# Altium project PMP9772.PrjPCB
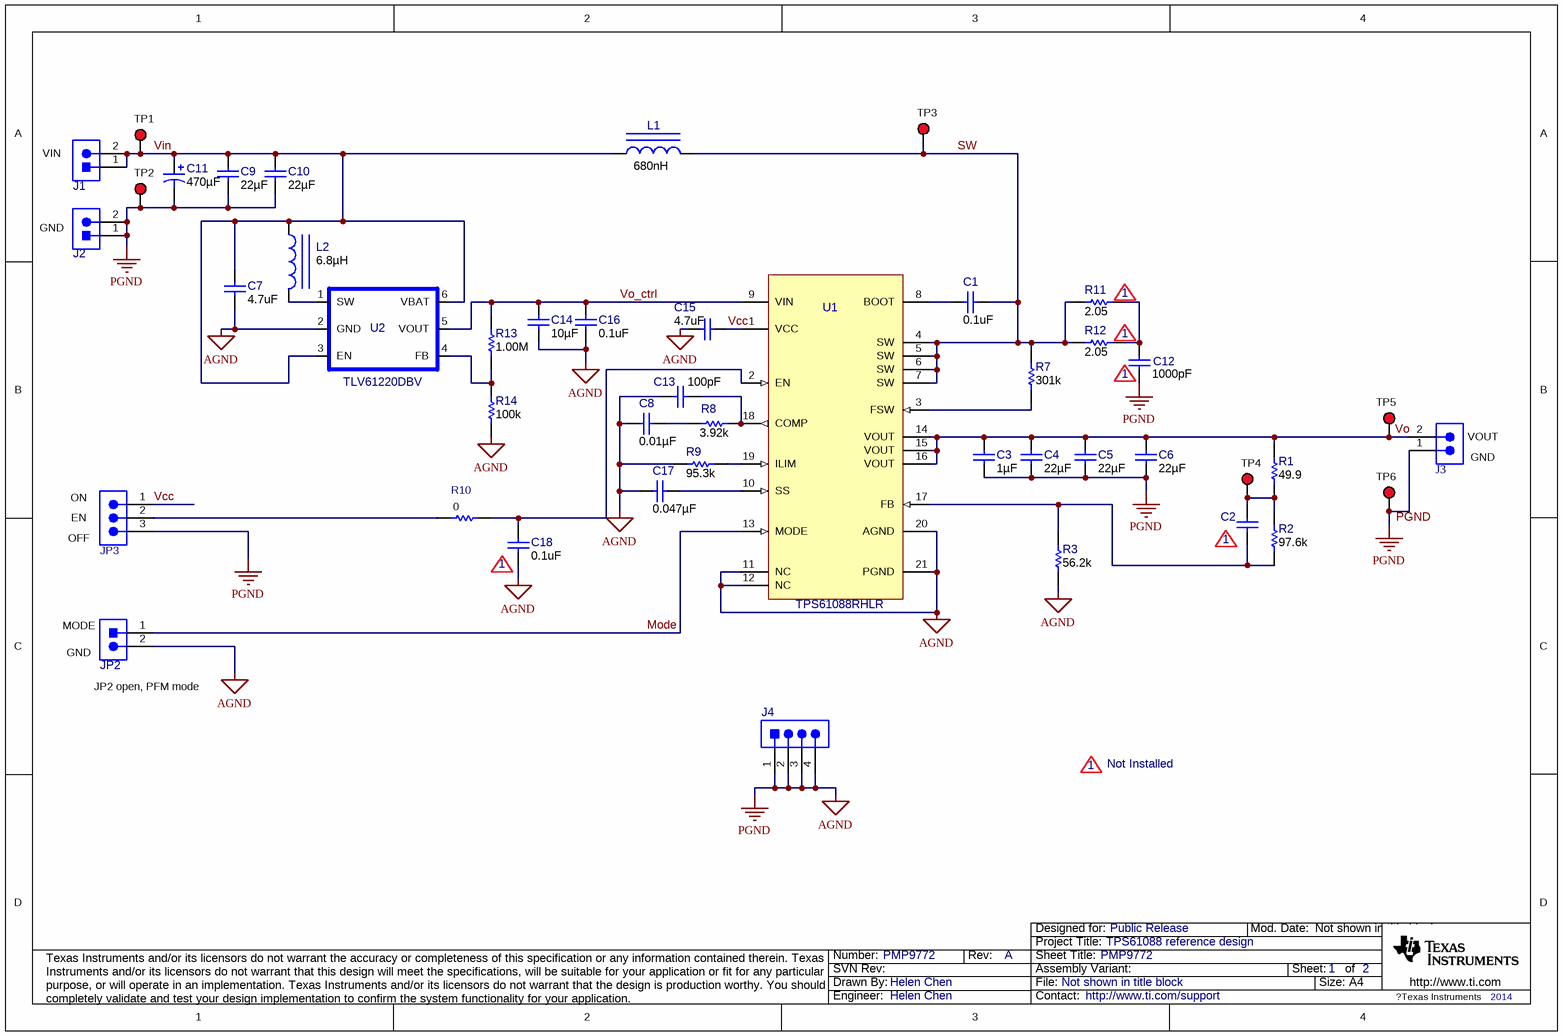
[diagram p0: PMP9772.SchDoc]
CopyrightYear: 2014; PCB_Layout: Helen Chen; PCB_Rev: A; PRJ_Customer: Public Release; PRJ_Engineer: Helen Chen; PRJ_Number: PMP9772; PRJ_Title: TPS61088 reference design; SCH_Rev: A; TechSupport: http://www.ti.com/support
2 sheets, 63 parts. Net scope: global (net labels, ports and power ports of the same name join across sheets).
Board file: PMP9772.PcbDoc
Sheets:
  PMP9772.SchDoc
  PMP9772_Hardware.SchDoc

## Sheet PMP9772.SchDoc: PMP9772
size A4; Date: Not shown in title block; ApprovedBy: Not shown in title block; CheckedBy: Not shown in title block; Author: Not shown in title block; CompanyName: TI; DrawnBy: Helen Chen; Engineer: Not shown in title block; Organization: Not shown in title block; Address1: Not shown in title block; Address2: Not shown in title block; Address3: Not shown in title block; Address4: Not shown in title block; DocumentNumber: 1; Revision: A; SheetNumber: 1; SheetTotal: 2; PageSetup: Record=PageOptions¦CenterHorizontal=True¦CenterVertical=True¦PrintScale=0.68¦XCorrection=1.00¦YCorrection=1.00¦PrintKind=0¦BorderSize=5000000¦LeftOffset=0¦BottomOffset=0¦Orientation=2¦PaperLength=1000¦PaperWidth=1000¦Scale=100¦PaperSource=15¦PrintQuality=600¦MediaType=1¦DitherType=10¦PaperKind=Letter¦PrintScaleMode=1

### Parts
C1  ValueDisplayed: 0.1uF  [0402]  (hidden comment: GRM155R61C104KA88D)
C2  GRM1555C1H470FA01D  [0402]  (value not drawn)
C3  ValueDisplayed: 1µF  [0603]  (hidden comment: GRM188R71E105KA12D)
C4  ValueDisplayed: 22µF  [1206]  (hidden comment: GRM31CR61C226KE15L)
C5  ValueDisplayed: 22µF  [1206]  (hidden comment: GRM31CR61C226KE15L)
C6  ValueDisplayed: 22µF  [1206]  (hidden comment: GRM31CR61C226KE15L)
C7  ValueDisplayed: 4.7uF  [0603]  (hidden comment: 0603ZD475KAT2A)
C8  ValueDisplayed: 0.01µF  [0402]  (hidden comment: GRM155R71C103KA01D)
C9  ValueDisplayed: 22µF  [0805_HV]  (hidden comment: C2012X5R0J226M)
C10  ValueDisplayed: 22µF  [0805_HV]  (hidden comment: C2012X5R0J226M)
C11  ValueDisplayed: 470µF  [7343-20]  (hidden comment: 6TPE470MAZU)
C12  ValueDisplayed: 1000pF  [0603]  (hidden comment: GRM188R72A102KA01D)
C13  ValueDisplayed: 100pF  [0402]  (hidden comment: GRM1555C1H101JA01D)
C14  ValueDisplayed: 10µF  [0603]  (hidden comment: C1608X5R1A106M)
C15  ValueDisplayed: 4.7uF  [0603]  (hidden comment: 0603ZD475KAT2A)
C16  ValueDisplayed: 0.1uF  [0402]  (hidden comment: GRM155R61C104KA88D)
C17  ValueDisplayed: 0.047µF  [0402]  (hidden comment: GRM155R71C473KA01D)
C18  ValueDisplayed: 0.1uF  [0402]  (hidden comment: GRM155R61C104KA88D)
J1  ED555/2DS  [TERM_BLK_ED555-2DS]  (value not drawn)
J2  ED555/2DS  [TERM_BLK_ED555-2DS]  (value not drawn)
J3  ED555/2DS  [TERM_BLK_ED555-2DS]  (value not drawn)
J4  TSW-104-07-G-S  [TSW-104-07-G-S]  (value not drawn)
JP2  PEC02SAAN  [CONN_PEC02SAAN]  (value not drawn)
JP3  PEC03SAAN  [CONN_PEC03SAAN]  (value not drawn)
L1  ValueDisplayed: 680nH  [CDMC8D28]  (hidden comment: CDMC8D28NP-R68MC)
L2  ValueDisplayed: 6.8µH  [LQH3NP_G0]  (hidden comment: LQH3NPN6R8NG0)
R1  value 49.9  [0402]  (hidden comment: CRCW040249R9FKED)
R2  ValueDisplayed: 97.6k  [0402]  (hidden comment: CRCW040297K6FKED)
R3  ValueDisplayed: 56.2k  [0402]  (hidden comment: CRCW040256K2FKED)
R7  ValueDisplayed: 301k  [0402]  (hidden comment: CRCW0402301KFKED)
R8  ValueDisplayed: 3.92k  [0402]  (hidden comment: CRCW04023K92FKED)
R9  ValueDisplayed: 95.3k  [0402]  (hidden comment: CRCW040295K3FKED)
R10  value 0  [0402]  (hidden comment: RC0402JR-070RL)
R11  ValueDisplayed: 2.05  [0603]  (hidden comment: CRCW06032R05FKEA)
R12  ValueDisplayed: 2.05  [0603]  (hidden comment: CRCW06032R05FKEA)
R13  ValueDisplayed: 1.00M  [0402]  (hidden comment: CRCW04021M00FKED)
R14  value 100k  [0402]  (hidden comment: CRCW0402100KFKED)
TP1  5010  [Keystone5010]  (value not drawn)
TP2  5010  [Keystone5010]  (value not drawn)
TP3  5010  [Keystone5010]  (value not drawn)
TP4  5010  [Keystone5010]  (value not drawn)
TP5  5010  [Keystone5010]  (value not drawn)
TP6  5010  [Keystone5010]  (value not drawn)
U1  TPS61088RHLR  [RHL0020A]
U2  TLV61220DBV  [DBV-6]

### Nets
AGND: C3.2 C4.2 C5.2 C6.2 C7.1 C8.2 C9.2 C10.2 C11.2(-) C12.2 C13.2 C14.2 C15.1 C16.2 C17.1 C18.2 J2.1 J2.2 J3.1 J4.1 J4.2 J4.3 J4.4 JP2.2 JP3.3 R3.1 R9.1 R14.1 TP2.1 TP6.1 U1.11(NC) U1.12(NC) U1.20(AGND) U1.21(PGND) U2.2(GND)  [also labelled PGND]
Mode: JP2.1 U1.13(MODE)
SW: C1.1 L1.2 R7.2 R11.1 R12.1 TP3.1 U1.4(SW) U1.5(SW) U1.6(SW) U1.7(SW)
Vcc: C15.2 JP3.1 U1.1(VCC)
Vin: C7.2 C9.1 C10.1 C11.1(+) J1.1 J1.2 L1.1 L2.1 TP1.1 U2.3(EN) U2.6(VBAT)
Vo: C3.1 C4.1 C5.1 C6.1 J3.2 R1.2 TP5.1 U1.14(VOUT) U1.15(VOUT) U1.16(VOUT)
Vo_ctrl: C14.1 C16.1 R13.2 U1.9(VIN) U2.5(VOUT)
NetC1_2: C1.2 U1.8(BOOT)
NetC2_1: C2.1 R1.1 R2.2 TP4.1
NetC2_2: C2.2 R2.1 R3.2 U1.17(FB)
NetC8_1: C8.1 R8.1
NetC12_1: C12.1 R11.2 R12.2
NetC13_1: C13.1 R8.2 U1.18(COMP)
NetC17_2: C17.2 U1.10(SS)
NetC18_1: C18.1 R10.1 U1.2(EN)
NetJP3_2: JP3.2 R10.2
NetL2_2: L2.2 U2.1(SW)
NetR7_1: R7.1 U1.3(FSW)
NetR9_2: R9.2 U1.19(ILIM)
NetR13_1: R13.1 R14.2 U2.4(FB)

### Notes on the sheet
- (near J1) VIN
- (near J2) GND
- (near R11) 1
- (near R12) 1
- (near C12) 1
- (near J3) VOUT
- (near JP3) EN
- (near JP3) ON
- (near J3) GND
- (near JP3) OFF
- (near C18) 1
- (near C2) 1
- (near JP2) MODE
- (near JP2) GND
- (near JP2) JP2 open, PFM mode
- 1
- Not Installed
- Labels drawn without touching a wire or pin: PGND

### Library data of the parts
C1 C16 C18 = GRM155R61C104KA88D: CAP, CERM, 0.1uF, 16V, +/-10%, X5R, 0402; Manufacturer: MuRata; Polarized: N; CompType: Capacitor; U/M: EA; Cap_F: 0.0000001; Tolerance_%: 10; Value1: Unknown; VDC_V: 16; TaMin_C: -55; TaMax_C: 85
C2 = GRM1555C1H470FA01D: CAP, CERM, 47 pF, 50 V, +/- 1%, C0G, 0402; Manufacturer: MuRata; Polarized: N; CompType: Capacitor; Value: 47pF; U/M: EA; Cap_F: 0.000000000047; Tolerance_%: 1; Value1: Unknown; VDC_V: 50; Value2: 50V; TaMin_C: -55; TaMax_C: 125
C3 = GRM188R71E105KA12D: CAP, CERM, 1 µF, 25 V, +/- 10%, X7R, 0603; Manufacturer: MuRata; Polarized: N; CompType: Capacitor; Value: 1uF; U/M: EA; Cap_F: 0.000001; Tolerance_%: 10; Value1: Unknown; VDC_V: 25; Value2: 25V; TaMin_C: -55; TaMax_C: 125
C4-C6 = GRM31CR61C226KE15L: CAP, CERM, 22 µF, 16 V, +/- 10%, X5R, 1206; Manufacturer: MuRata; Polarized: N; CompType: Capacitor; Value: 22uF; U/M: EA; Cap_F: 0.000022; Tolerance_%: 10; Value1: Unknown; VDC_V: 16; Value2: 16V; TaMin_C: -55; TaMax_C: 85
C7 C15 = 0603ZD475KAT2A: CAP, CERM, 4.7uF, 10V, +/-10%, X5R, 0603; Manufacturer: AVX; Polarized: N; CompType: Capacitor; U/M: EA; Cap_F: 0.0000047; Tolerance_%: 10; Value1: Unknown; TaMin_C: -55; TaMax_C: 85
C8 = GRM155R71C103KA01D: CAP, CERM, 0.01 µF, 16 V, +/- 10%, X7R, 0402; Manufacturer: MuRata; Polarized: N; CompType: Capacitor; Value: 0.01uF; U/M: EA; Cap_F: 0.00000001; Tolerance_%: 10; Value1: Unknown; VDC_V: 16; Value2: 16V; TaMin_C: -55; TaMax_C: 125
C9 C10 = C2012X5R0J226M: CAP, CERM, 22 µF, 6.3 V, +/- 20%, X5R, 0805; Manufacturer: TDK; Polarized: N; CompType: Capacitor; Value: 22uF; U/M: EA; Cap_F: 0.000022; Tolerance_%: 20; ESR_ohm: 0.0018; Value1: 0.0018 ohm; VDC_V: 6.3; Value2: 6.3V; TaMin_C: -55; TaMax_C: 85; Cap_Case: 0805
C11 = 6TPE470MAZU: CAP, TA, 470 µF, 6.3 V, +/- 10%, 0.035 ohm, SMD; Manufacturer: Panasonic; Polarized: Y; CompType: Capacitor; Value: 470uF; U/M: EA; Cap_F: 0.00047; Tolerance_%: 10; VDC_V: 6.3; Value2: 6.3V; ESR_ohm: 0.035; IRMS_A: 1.7; TaMin_C: -55; TaMax_C: 105; Cap_Case: D
C12 = GRM188R72A102KA01D: CAP, CERM, 1000 pF, 100 V, +/- 10%, X7R, 0603; Manufacturer: MuRata; Polarized: N; CompType: Capacitor; Value: 1000pF; U/M: EA; Cap_F: 0.000000001; Tolerance_%: 10; Value1: Unknown; VDC_V: 100; Value2: 100V; TaMin_C: -55; TaMax_C: 125
C13 = GRM1555C1H101JA01D: CAP, CERM, 100 pF, 50 V, +/- 5%, C0G/NP0, 0402; Manufacturer: MuRata; Polarized: N; CompType: Capacitor; Value: 100pF; U/M: EA; Cap_F: 0.0000000001; Tolerance_%: 5; Value1: Unknown; VDC_V: 50; Value2: 50V; TaMin_C: -55; TaMax_C: 125
C14 = C1608X5R1A106M: CAP, CERM, 10 µF, 10 V, +/- 20%, X5R, 0603; Manufacturer: TDK; Polarized: N; CompType: Capacitor; Value: 10uF; U/M: EA; Cap_F: 0.00001; Tolerance_%: 20; ESR_ohm: 0.0078; Value1: 0.0078 ohm; VDC_V: 10; Value2: 10V; IRMS_A: 1.85; TaMin_C: -55; TaMax_C: 85
C17 = GRM155R71C473KA01D: CAP, CERM, 0.047 µF, 16 V, +/- 10%, X7R, 0402; Manufacturer: MuRata; Polarized: N; CompType: Capacitor; Value: 0.047uF; U/M: EA; Cap_F: 0.000000047; Tolerance_%: 10; Value1: Unknown; VDC_V: 16; Value2: 16V; TaMin_C: -55; TaMax_C: 125
J1-J3 = ED555/2DS: Terminal Block, 6A, 3.5mm Pitch, 2-Pos, TH; Manufacturer: On-Shore Technology; SymbolCreator: a0412235; CompType: Connector; U/M: EA
J4 = TSW-104-07-G-S: Header, 100mil, 4x1, Gold, TH; Manufacturer: Samtec; SymbolCreator: a0412235; U/M: EA
JP2 = PEC02SAAN: Header, 100mil, 2x1, Tin, TH; Manufacturer: Sullins Connector Solutions; SymbolCreator: a0412235; U/M: EA
JP3 = PEC03SAAN: Header, 100mil, 3x1, Tin plated, TH; Manufacturer: Sullins Connector Solutions; SymbolCreator: a0799628; U/M: EA
L1 = CDMC8D28NP-R68MC: Inductor, Shielded Drum Core, Metal Composite, 680 nH, 15.4 A, 0.00384 ohm, SMD; Manufacturer: Sumida; Value: 680nH; Ind_H: 680.0E-9; Imax_A: 15.4; Irms: 15.4A @ 40C rise; Isat: 16A @ 20% inductance drop; Value2: 15.4A
L2 = LQH3NPN6R8NG0: Inductor, Wirewound, Ferrite, 6.8 µH, 0.65 A, 0.45 ohm, SMD; Manufacturer: MuRata; Value: 6.8uH; Ind_H: 6.8E-6; Imax_A: 0.65; Irms: 0.71A @ 40C rise; Isat: 0.65A @ 30% inductance drop; DCR_ohm: 0.45; Value2: 0.65A
R1 = CRCW040249R9FKED: RES, 49.9 ohm, 1%, 0.063W, 0402; Manufacturer: Vishay-Dale; CompType: Resistor; Value_Code: 49R9; Tolerance_%: 1; Power_W: 0.063; VDC_V: 50; TempCo: 100 ppm/C; EIA_Code: E96; U/M: EA
R2 = CRCW040297K6FKED: RES, 97.6 k, 1%, 0.063 W, 0402; Manufacturer: Vishay-Dale; CompType: Resistor; Value: 97.6k; Res_ohm: 97600; Value_Code: 97k6; Tolerance_%: 1; Power_W: 0.063; Value2: 0.063W; VDC_V: 50; TempCo: 100 ppm/C; EIA_Code: E96; U/M: EA
R3 = CRCW040256K2FKED: RES, 56.2 k, 1%, 0.063 W, 0402; Manufacturer: Vishay-Dale; CompType: Resistor; Value: 56.2k; Res_ohm: 56200; Value_Code: 56k2; Tolerance_%: 1; Power_W: 0.063; Value2: 0.063W; VDC_V: 50; TempCo: 100 ppm/C; EIA_Code: E96; U/M: EA
R7 = CRCW0402301KFKED: RES, 301 k, 1%, 0.063 W, 0402; Manufacturer: Vishay-Dale; CompType: Resistor; Value: 301k; Res_ohm: 301000; Tolerance_%: 1; Power_W: 0.063; Value2: 0.063W; VDC_V: 50; TempCo: 100 ppm/C; EIA_Code: E96; U/M: EA
R8 = CRCW04023K92FKED: RES, 3.92 k, 1%, 0.063 W, 0402; Manufacturer: Vishay-Dale; CompType: Resistor; Value: 3.92k; Res_ohm: 3920; Value_Code: 3k92; Tolerance_%: 1; Power_W: 0.063; Value2: 0.063W; VDC_V: 50; TempCo: 100 ppm/C; EIA_Code: E96; U/M: EA
R9 = CRCW040295K3FKED: RES, 95.3 k, 1%, 0.063 W, 0402; Manufacturer: Vishay-Dale; CompType: Resistor; Value: 95.3k; Res_ohm: 95300; Value_Code: 95k3; Tolerance_%: 1; Power_W: 0.063; Value2: 0.063W; VDC_V: 50; TempCo: 100 ppm/C; EIA_Code: E96; U/M: EA
R10 = RC0402JR-070RL: RES, 0 ohm, 5%, 0.063W, 0402; Manufacturer: Yageo America; CompType: Resistor; Value_Code: 0000; Tolerance_%: 5; Power_W: 0.063; VDC_V: 50; TempCo: 200 ppm/C; EIA_Code: E24; U/M: EA
R11 R12 = CRCW06032R05FKEA: RES, 2.05, 1%, 0.1 W, 0603; Manufacturer: Vishay-Dale; CompType: Resistor; Value: 2.05; Value_Code: 2R05; Tolerance_%: 1; Power_W: 0.1; Value2: 0.1W; VDC_V: 75; TempCo: 100 ppm/C; EIA_Code: E96; U/M: EA
R13 = CRCW04021M00FKED: RES, 1.00 M, 1%, 0.063 W, 0402; Manufacturer: Vishay-Dale; CompType: Resistor; Value: 1.00Meg; Res_ohm: 1000000; Value_Code: 1M00; Tolerance_%: 1; Power_W: 0.063; Value2: 0.063W; VDC_V: 50; TempCo: 100 ppm/C; EIA_Code: E96; U/M: EA
R14 = CRCW0402100KFKED: RES, 100k ohm, 1%, 0.063W, 0402; Manufacturer: Vishay-Dale; CompType: Resistor; Res_ohm: 100000; Tolerance_%: 1; Power_W: 0.063; VDC_V: 50; TempCo: 100 ppm/C; EIA_Code: E96; U/M: EA
TP1-TP6 = 5010: Test Point, TH, Multipurpose, Red; Manufacturer: Keystone; CompType: Test Point Loop; U/M: EA
U1 = TPS61088RHLR: 13.2-V Output, Synchronous Boost Converter with 10-A Switch, RHL0020A; Alternate PartNumber: TPS61088RHLT; Manufacturer: Texas Instruments; SymbolCreator: Altium; CompType: IC; U/M: EA
U2 = TLV61220DBV: IC, High Efficient, Tiny 1Cell LiIon or 1-3 Cells Alk/Nixx Boost Converter; Manufacturer: TI; Alternate Manufacturer: None; Area: 24336

## Sheet PMP9772_Hardware.SchDoc
size A4; Date: Not shown in title block; ApprovedBy: Not shown in title block; CheckedBy: Not shown in title block; Author: Not shown in title block; CompanyName: Not shown in title block; Engineer: Not shown in title block; Organization: Not shown in title block; Address1: Not shown in title block; Address2: Not shown in title block; Address3: Not shown in title block; Address4: Not shown in title block; DocumentNumber: 2; Revision: Use project parameter SCH_Rev; SheetNumber: 2; SheetTotal: 2; PageSetup: Record=PageOptions¦CenterHorizontal=True¦CenterVertical=True¦PrintScale=0.69¦XCorrection=1.00¦YCorrection=1.00¦PrintKind=0¦BorderSize=5000000¦LeftOffset=0¦BottomOffset=0¦Orientation=2¦PaperLength=1000¦PaperWidth=1000¦Scale=100¦PaperSource=15¦PrintQuality=600¦MediaType=1¦DitherType=10¦PaperKind=Letter¦PrintScaleMode=1
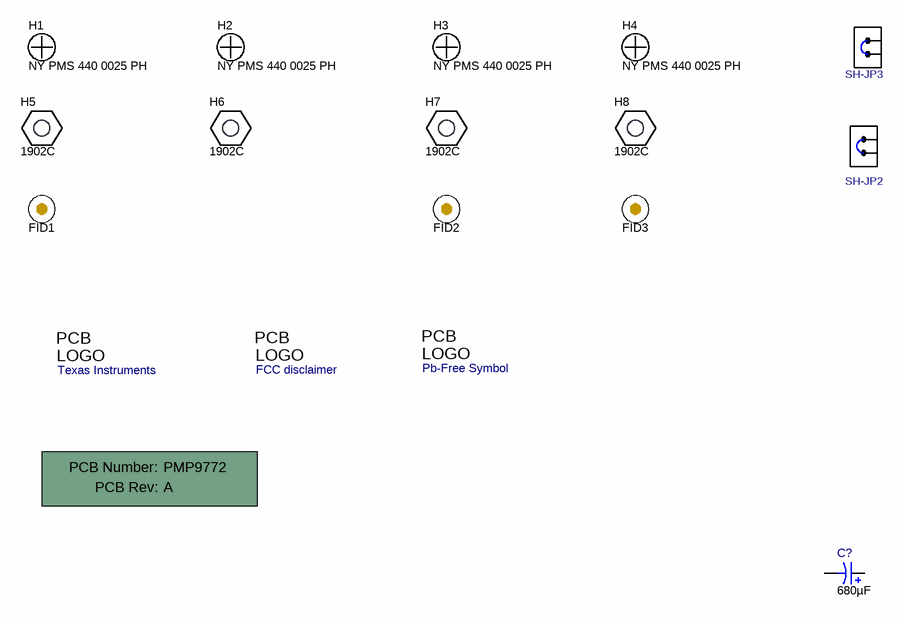
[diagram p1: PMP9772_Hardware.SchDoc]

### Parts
!PCB  Printed Circuit Board  (value not drawn)  (mechanical)
C?  ValueDisplayed: 680µF  [7343-43]  (hidden comment: TPSE687K006R0045)
FID1  Fiducial  [Fiducial10-20]  (value not drawn)
FID2  Fiducial  [Fiducial10-20]  (value not drawn)
FID3  Fiducial  [Fiducial10-20]  (value not drawn)
H1  NY PMS 440 0025 PH  [NY PMS 440 0025 PH]
H2  NY PMS 440 0025 PH  [NY PMS 440 0025 PH]
H3  NY PMS 440 0025 PH  [NY PMS 440 0025 PH]
H4  NY PMS 440 0025 PH  [NY PMS 440 0025 PH]
H5  1902C  [Keystone_1902C]
H6  1902C  [Keystone_1902C]
H7  1902C  [Keystone_1902C]
H8  1902C  [Keystone_1902C]
Logo1  Texas Instruments  [TI_Stacked_Overlay_Small]  (no BOM)
Logo2  FCC disclaimer  [FCC_disclaimer]  (no BOM)
Logo3  Pb-Free Symbol  [Pb-Free_Overlay_Medium]  (no BOM)
SH-JP2  969102-0000-DA  [SNT-100-BK-G]  (value not drawn)
SH-JP3  969102-0000-DA  [SNT-100-BK-G]  (value not drawn)

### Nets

Not connected (* = marked no-connect by the designer): C? 1(+) 2(-)

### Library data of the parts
!PCB = PCB: Manufacturer: Any; PartNumber: PMP9772; SymbolCreator: a0412235
C? = TPSE687K006R0045: CAP, TA, 680 µF, 6.3 V, +/- 10%, 0.045 ohm, SMD; Manufacturer: AVX; Polarized: Y; CompType: Capacitor; Value: 680uF; U/M: EA; Cap_F: 0.00068; Tolerance_%: 10; VDC_V: 6.3; Value2: 6.3V; ESR_ohm: 0.045; IRMS_A: 1.723; TaMin_C: -55; TaMax_C: 125; Cap_Case: E
FID1-FID3 = Fiducial: Fiducial mark.  There is nothing to buy or mount.; SymbolCreator: codlsc
H1-H4 = NY PMS 440 0025 PH: Machine Screw, Round, #4-40 x 1/4, Nylon, Philips panhead; Manufacturer: B&F Fastener Supply; CompType: Hardware; SymbolCreator: codlsc; U/M: EA
H5-H8 = 1902C: Standoff, Hex, 0.5"L #4-40 Nylon; Manufacturer: Keystone; CompType: Hardware
Logo1 = TI_Logo: Texas Instrument Corporate Signature; SymbolCreator: codlsc
Logo2 = FCC_disclaimer: SymbolCreator: codlsc
Logo3 = Pb-Free: SymbolCreator: a0412235
SH-JP2 SH-JP3 = 969102-0000-DA: Shunt, 100mil, Gold plated, Black; Manufacturer: 3M; Alternate Manufacturer: Samtec; Value: 1x2; Note: You can "mate" this to a header by matching the designator.  i.e. use SH-J3 for header J3

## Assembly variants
001: not fitted C2 C11 C12 C18 FID1 FID2 FID3 R11 R12
002: not fitted C2 C12 C18 FID1 FID2 FID3 R11 R12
